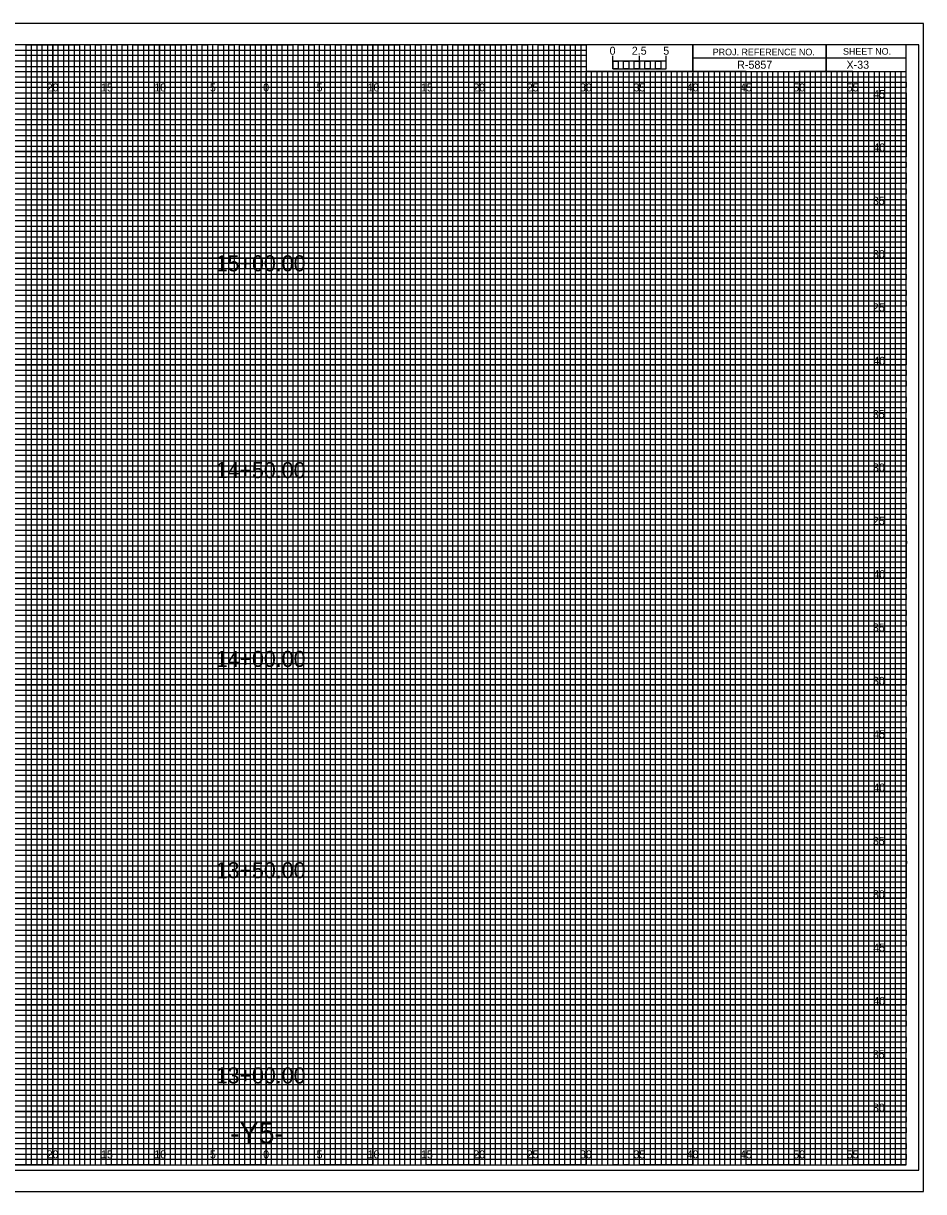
# Model space of a CAD drawing. Extents: x -7 to 162, y 107 to 217.
# Drawn here: x 77.2 to 161.7, y 107.5 to 217 of the extents above; entities that cross this region are included whole.
import ezdxf

# ---------------------------------------------------------------- set-up
doc = ezdxf.new("R2010")
doc.units = 0
for name, color, linetype in [('Exist Cross Section Cell', 7, 'Continuous'), ('Exist XS Center Line Elevation Label', 7, 'Continuous'), ('Exist XS Ground Line', 7, 'Continuous'), ('Prop CMT Pvmt Course 1', 7, 'Continuous'), ('Prop CMT Pvmt Course 1 Wedge', 7, 'Continuous'), ('Prop CMT Pvmt Course 2', 7, 'Continuous'), ('Prop CMT Pvmt Course 2 Wedge', 7, 'Continuous'), ('Prop CMT Pvmt Course 3', 7, 'Continuous'), ('Prop CMT Pvmt Surface', 7, 'Continuous'), ('Prop CMT Pvmt Surface Shoulder', 7, 'Continuous'), ('Prop CMT Pvmt Wedge Surface 1', 7, 'Continuous'), ('Prop CMT Shld Paved Course 1', 7, 'Continuous'), ('Prop CMT Shld Paved Course 2', 7, 'Continuous'), ('Prop CMT Shld Paved Course 3', 7, 'Continuous'), ('Prop CMT Slope Grass', 7, 'Continuous'), ('Prop CMT Subgrade Earthwork', 7, 'Continuous'), ('Scratch_Level_0', 7, 'Continuous')]:
    doc.layers.add(name, color=color, linetype=linetype)

msp = doc.modelspace()

# ---------------------------------------------------------------- linework, layer by layer
at = {"layer": 'Exist XS Center Line Elevation Label'}
for points in [[(72.5, 110), (77.5, 110), (77.5, 215), (82.5, 215), (82.5, 110), (87.5, 110), (87.5, 215), (92.5, 215), (92.5, 110), (97.5, 110), (97.5, 215), (102.5, 215), (102.5, 110), (107.5, 110), (107.5, 215), (112.5, 215), (112.5, 110), (117.5, 110), (117.5, 215), (122.5, 215), (122.5, 110), (127.5, 110), (127.5, 215), (129.97, 215), (130, 215), (130, 212.5), (132.5, 212.5), (132.5, 110), (137.5, 110), (137.5, 212.5), (142.5, 212.5), (142.5, 110), (147.5, 110), (147.5, 212.5), (152.5, 212.5), (152.5, 110), (157.5, 110), (157.5, 212.5)], [(0, 212.5), (137.5, 212.5)], [(0, 202.5), (160, 202.5), (160, 207.5), (0, 207.5)], [(0, 192.5), (160, 192.5), (160, 197.5), (0, 197.5)], [(0, 182.5), (160, 182.5), (160, 187.5), (0, 187.5)], [(0, 172.5), (160, 172.5), (160, 177.5), (0, 177.5)], [(0, 162.5), (160, 162.5), (160, 167.5), (0, 167.5)], [(0, 152.5), (160, 152.5), (160, 157.5), (0, 157.5)], [(0, 142.5), (160, 142.5), (160, 147.5), (0, 147.5)], [(0, 132.5), (160, 132.5), (160, 137.5), (0, 137.5)], [(0, 122.5), (160, 122.5), (160, 127.5), (0, 127.5)], [(0, 112.5), (160, 112.5), (160, 117.5), (0, 117.5)]]:
    msp.add_lwpolyline(points, dxfattribs=at)
at = {"layer": 'Exist XS Ground Line'}
for p, q in [((85, 215), (80, 215)), ((80, 215), (80, 110)), ((85, 110), (85, 215)), ((95, 215), (90, 215)), ((90, 215), (90, 110)), ((95, 110), (95, 215)), ((105, 215), (100, 215)), ((100, 215), (100, 110)), ((105, 110), (105, 215)), ((115, 215), (110, 215)), ((110, 215), (110, 110)), ((115, 110), (115, 215)), ((125, 215), (120, 215)), ((120, 215), (120, 110)), ((125, 110), (125, 215)), ((130, 215), (130, 110)), ((135, 110), (135, 212.5)), ((145, 212.5), (140, 212.5)), ((140, 212.5), (140, 110)), ((145, 110), (145, 212.5)), ((155, 212.5), (150, 212.5)), ((150, 212.5), (150, 110)), ((155, 110), (155, 212.5)), ((80, 110), (75, 110)), ((90, 110), (85, 110)), ((100, 110), (95, 110)), ((110, 110), (105, 110)), ((120, 110), (115, 110)), ((130, 110), (125, 110)), ((140, 110), (135, 110)), ((150, 110), (145, 110)), ((160, 110), (155, 110)), ((160, 110), (160, 110))]:
    msp.add_line(p, q, dxfattribs=at)
for points in [[(0, 210), (160, 210), (160, 205), (0, 205)], [(0, 200), (160, 200), (160, 195), (0, 195)], [(0, 190), (160, 190), (160, 185), (0, 185)], [(0, 180), (160, 180), (160, 175), (0, 175)], [(0, 170), (160, 170), (160, 165), (0, 165)], [(0, 160), (160, 160), (160, 155), (0, 155)], [(0, 150), (160, 150), (160, 145), (0, 145)], [(0, 140), (160, 140), (160, 135), (0, 135)], [(0, 130), (160, 130), (160, 125), (0, 125)], [(0, 120), (160, 120), (160, 115), (0, 115)]]:
    msp.add_lwpolyline(points, dxfattribs=at)
at = {"layer": 'Prop CMT Pvmt Course 1'}
msp.add_lwpolyline([(-5.4, 109.5), (161.2, 109.5), (161.2, 215), (-5.4, 215)], close=True, dxfattribs=at)
at = {"layer": 'Prop CMT Pvmt Course 2'}
for p, q in [((80, 110), (80, 215)), ((85, 110), (85, 215)), ((90, 110), (90, 215)), ((95, 110), (95, 215)), ((100, 110), (100, 215)), ((105, 110), (105, 215)), ((110, 110), (110, 215)), ((115, 110), (115, 215)), ((120, 110), (120, 215)), ((125, 110), (125, 215)), ((130, 110), (130, 212.34)), ((135, 110), (135, 212.34)), ((140, 110), (140, 212.34)), ((145, 110), (145, 212.34)), ((150, 110), (150, 212.34)), ((155, 110), (155, 212.34)), ((0, 210), (160, 210)), ((0, 205), (160, 205)), ((0, 200), (160, 200)), ((0, 195), (160, 195)), ((0, 190), (160, 190)), ((0, 185), (160, 185)), ((0, 180), (160, 180)), ((0, 175), (160, 175)), ((0, 170), (160, 170)), ((0, 165), (160, 165)), ((0, 160), (160, 160)), ((0, 155), (160, 155)), ((0, 150), (160, 150)), ((0, 145), (160, 145)), ((0, 140), (160, 140)), ((0, 135), (160, 135)), ((0, 130), (160, 130)), ((0, 125), (160, 125)), ((0, 120), (160, 120)), ((0, 115), (160, 115))]:
    msp.add_line(p, q, dxfattribs=at)
at = {"layer": 'Prop CMT Pvmt Course 3'}
for p, q in [((161.65, 217), (-6.7, 217)), ((-6.7, 107.5), (161.65, 107.5))]:
    msp.add_line(p, q, dxfattribs=at)
at = {"layer": 'Prop CMT Shld Paved Course 1'}
for p, q in [((133.5, 212.5), (133, 212.5)), ((133, 212.5), (133, 110)), ((133.5, 110), (133.5, 212.5)), ((134.5, 212.5), (134, 212.5)), ((134, 212.5), (134, 110)), ((134.5, 110), (134.5, 212.5)), ((133, 110), (132.5, 110)), ((134, 110), (133.5, 110))]:
    msp.add_line(p, q, dxfattribs=at)
for points in [[(77.5, 110), (78, 110), (78, 215), (78.5, 215), (78.5, 110)], [(78.5, 110), (79, 110), (79, 215), (79.5, 215), (79.5, 110)], [(80, 110), (80.5, 110), (80.5, 215), (81, 215), (81, 110)], [(81, 110), (81.5, 110), (81.5, 215), (82, 215), (82, 110)], [(82.5, 110), (83, 110), (83, 215), (83.5, 215), (83.5, 110)], [(83.5, 110), (84, 110), (84, 215), (84.5, 215), (84.5, 110)], [(85, 110), (85.5, 110), (85.5, 215), (86, 215), (86, 110)], [(86, 110), (86.5, 110), (86.5, 215), (87, 215), (87, 110)], [(87.5, 110), (88, 110), (88, 215), (88.5, 215), (88.5, 110)], [(88.5, 110), (89, 110), (89, 215), (89.5, 215), (89.5, 110)], [(90, 110), (90.5, 110), (90.5, 215), (91, 215), (91, 110)], [(91, 110), (91.5, 110), (91.5, 215), (92, 215), (92, 110)], [(92.5, 110), (93, 110), (93, 215), (93.5, 215), (93.5, 110)], [(93.5, 110), (94, 110), (94, 215), (94.5, 215), (94.5, 110)], [(95, 110), (95.5, 110), (95.5, 215), (96, 215), (96, 110)], [(96, 110), (96.5, 110), (96.5, 215), (97, 215), (97, 110)], [(97.5, 110), (98, 110), (98, 215), (98.5, 215), (98.5, 110)], [(98.5, 110), (99, 110), (99, 215), (99.5, 215), (99.5, 110)], [(100, 110), (100.5, 110), (100.5, 215), (101, 215), (101, 110)], [(101, 110), (101.5, 110), (101.5, 215), (102, 215), (102, 110)], [(102.5, 110), (103, 110), (103, 215), (103.5, 215), (103.5, 110)], [(103.5, 110), (104, 110), (104, 215), (104.5, 215), (104.5, 110)], [(105, 110), (105.5, 110), (105.5, 215), (106, 215), (106, 110)], [(106, 110), (106.5, 110), (106.5, 215), (107, 215), (107, 110)], [(107.5, 110), (108, 110), (108, 215), (108.5, 215), (108.5, 110)], [(108.5, 110), (109, 110), (109, 215), (109.5, 215), (109.5, 110)], [(110, 110), (110.5, 110), (110.5, 215), (111, 215), (111, 110)], [(111, 110), (111.5, 110), (111.5, 215), (112, 215), (112, 110)], [(112.5, 110), (113, 110), (113, 215), (113.5, 215), (113.5, 110)], [(113.5, 110), (114, 110), (114, 215), (114.5, 215), (114.5, 110)], [(115, 110), (115.5, 110), (115.5, 215), (116, 215), (116, 110)], [(116, 110), (116.5, 110), (116.5, 215), (117, 215), (117, 110)], [(117.5, 110), (118, 110), (118, 215), (118.5, 215), (118.5, 110)], [(118.5, 110), (119, 110), (119, 215), (119.5, 215), (119.5, 110)], [(120, 110), (120.5, 110), (120.5, 215), (121, 215), (121, 110)], [(121, 110), (121.5, 110), (121.5, 215), (122, 215), (122, 110)], [(122.5, 110), (123, 110), (123, 215), (123.5, 215), (123.5, 110)], [(123.5, 110), (124, 110), (124, 215), (124.5, 215), (124.5, 110)], [(125, 110), (125.5, 110), (125.5, 215), (126, 215), (126, 110)], [(126, 110), (126.5, 110), (126.5, 215), (127, 215), (127, 110)], [(127.5, 110), (128, 110), (128, 215), (128.5, 215), (128.5, 110)], [(128.5, 110), (129, 110), (129, 215), (129.5, 215), (129.5, 110)], [(130, 110), (130.5, 110), (130.5, 212.5), (131.01, 212.5), (131.01, 110)], [(131, 110), (131.5, 110), (131.5, 212.5), (132, 212.5), (132, 110)], [(135, 110), (135.49, 110), (135.49, 212.5), (136, 212.5), (136, 110)], [(136, 110), (136.5, 110), (136.5, 212.5), (137.03, 212.5), (137.03, 110)], [(137.5, 110), (138, 110), (138, 212.5), (138.5, 212.5), (138.5, 110)], [(138.5, 110), (139, 110), (139, 212.5), (139.5, 212.5), (139.5, 110)], [(140, 110), (140.5, 110), (140.5, 212.5), (141, 212.5), (141, 110)], [(141, 110), (141.5, 110), (141.5, 212.5), (142, 212.5), (142, 110)], [(142.5, 110), (143, 110), (143, 212.5), (143.5, 212.5), (143.5, 110)], [(143.5, 110), (144, 110), (144, 212.5), (144.5, 212.5), (144.5, 110)], [(145, 110), (145.5, 110), (145.5, 212.5), (146, 212.5), (146, 110)], [(146, 110), (146.5, 110), (146.5, 212.5), (147, 212.5), (147, 110)], [(147.5, 110), (148, 110), (148, 212.5), (148.5, 212.5), (148.5, 110)], [(148.5, 110), (149, 110), (149, 212.5), (149.5, 212.5), (149.5, 110)], [(150, 110), (150.5, 110), (150.5, 212.5), (151, 212.5), (151, 110)], [(151, 110), (151.5, 110), (151.5, 212.5), (152, 212.5), (152, 110)], [(152.5, 110), (153, 110), (153, 212.5), (153.5, 212.5), (153.5, 110)], [(153.5, 110), (154, 110), (154, 212.5), (154.5, 212.5), (154.5, 110)], [(155, 110), (155.5, 110), (155.5, 212.5), (156, 212.5), (156, 110)], [(156, 110), (156.5, 110), (156.5, 212.5), (157, 212.5), (157, 110)], [(157.5, 110), (158, 110), (158, 212.5), (158.5, 212.5), (158.5, 110)], [(158.5, 110), (159, 110), (159, 212.5), (159.5, 212.5), (159.5, 110)]]:
    msp.add_lwpolyline(points, dxfattribs=at)
at = {"layer": 'Prop CMT Shld Paved Course 2'}
for p, q in [((132.5, 212.75), (132.5, 213.95)), ((132.5, 213.45), (132.5, 213.95)), ((135, 212.75), (135, 213.95)), ((137.5, 212.75), (137.5, 213.95)), ((137.5, 213.45), (137.5, 213.95))]:
    msp.add_line(p, q, dxfattribs=at)
for points in [[(137.5, 213.45), (132.5, 213.45), (132.5, 212.75), (137.5, 212.75)], [(132.5, 213.45), (133, 213.45), (133, 212.75), (132.5, 212.75)], [(133.5, 213.45), (134, 213.45), (134, 212.75), (133.5, 212.75)], [(134.5, 213.45), (135, 213.45), (135, 212.75), (134.5, 212.75)], [(135.5, 213.45), (136, 213.45), (136, 212.75), (135.5, 212.75)], [(136.5, 213.45), (137, 213.45), (137, 212.75), (136.5, 212.75)]]:
    msp.add_lwpolyline(points, close=True, dxfattribs=at)
at = {"layer": 'Prop CMT Shld Paved Course 3'}
msp.add_lwpolyline([(-6.7, 107.5), (161.65, 107.5), (161.65, 217), (-6.7, 217)], close=True, dxfattribs=at)
at = {"layer": 'Prop CMT Slope Grass'}
for p, q in [((152.5, 215), (152.5, 212.5)), ((152.5, 212.5), (152.5, 215)), ((160, 213.75), (140, 213.75)), ((140, 213.75), (140, 212.5)), ((140, 212.5), (160, 212.5))]:
    msp.add_line(p, q, dxfattribs=at)
for points in [[(160, 215), (0, 215), (0, 110), (160, 110)], [(140, 215), (130, 215), (130, 212.52), (140, 212.52)], [(160, 215), (140, 215), (140, 212.5), (160, 212.5)]]:
    msp.add_lwpolyline(points, close=True, dxfattribs=at)
at = {"layer": 'Scratch_Level_0'}
for p, q in [((0, 214.5), (130, 214.5)), ((130, 213.99), (0, 213.99)), ((130, 214.5), (130, 213.99)), ((0, 213.5), (130, 213.5)), ((130, 212.94), (0, 212.94)), ((130, 213.5), (130, 212.94)), ((0, 212), (160, 212))]:
    msp.add_line(p, q, dxfattribs=at)
for points in [[(0, 211.5), (135, 211.5), (160, 211.5), (160, 211), (0, 211)], [(0, 210.5), (160, 210.5), (160, 209.5), (0, 209.5)], [(0, 209), (160, 209), (160, 208.5), (0, 208.49)], [(0, 208), (160, 208), (160, 207), (0, 207)], [(0, 206.5), (160, 206.5), (160, 206), (0, 206)], [(0, 205.5), (160, 205.5), (160, 204.5), (0, 204.5)], [(0, 204), (160, 204), (160, 203.5), (0, 203.5)], [(0, 203), (160, 203), (160, 202), (0, 202)], [(0, 201.5), (160, 201.5), (160, 201), (0, 201)], [(0, 200.5), (160, 200.5), (160, 199.5), (0, 199.5)], [(0, 199), (160, 199), (160, 198.5), (0, 198.5)], [(0, 198), (160, 198), (160, 196.97), (160, 196.5), (160, 196), (0, 196)], [(0, 197), (160, 197), (160, 196.5), (0, 196.5)], [(0, 195.5), (160, 195.5), (160, 194.5), (0, 194.52)], [(0, 194.52), (160, 194.5), (160, 194), (0, 194)], [(0, 193.5), (160, 193.5), (160, 193), (0, 193)], [(0, 192), (160, 192), (160, 191.5), (0, 191.5)], [(0, 191), (160, 191), (160, 190.5), (0, 190.5)], [(-0.04, 189.44), (160, 189.44), (160, 188.94), (-0.04, 188.94)], [(0, 188.5), (160, 188.5), (160, 188), (0, 188)], [(0, 187), (160, 187), (160, 186.5), (0, 186.5)], [(0, 186), (160, 186), (160, 185.5), (0, 185.5)], [(0, 184.5), (160, 184.5), (160, 184), (0, 184)], [(0, 183.5), (160, 183.5), (160, 183), (0, 183)], [(0, 182), (160, 182), (160, 181.5), (0, 181.5)], [(0, 181), (160, 181), (160, 180.5), (0, 180.5)], [(0, 179.5), (160, 179.5), (160, 178.99), (0, 179)], [(0, 178.5), (160, 178.5), (160, 178), (0, 178)], [(0, 177), (160, 177), (160, 176.5), (0, 176.5)], [(0, 176), (160, 176), (160, 175.5), (0, 175.5)], [(0, 174.5), (160, 174.5), (160, 174), (0, 174)], [(0, 173.5), (160, 173.5), (160, 173), (0, 173)], [(0, 172), (160, 172), (160, 171.5), (0, 171.5)], [(0, 171), (160, 171), (160, 170.5), (0, 170.5)], [(0, 169.5), (160, 169.5), (160, 169), (0, 169)], [(0, 168.5), (160.03, 168.46), (160, 168), (0, 168)], [(0, 167), (160, 167), (160, 166.5), (0, 166.5)], [(0, 166), (160, 166), (160, 165.5), (0, 165.5)], [(0, 164.5), (160, 164.5), (160, 164), (0, 164)], [(0, 163.5), (160, 163.5), (160, 163), (0, 163)], [(0, 162), (160, 162), (160, 161.5), (0, 161.5)], [(0, 161), (160, 161), (160, 160.5), (0, 160.5)], [(0, 159.5), (160, 159.5), (160, 159), (0, 159)], [(0, 158.5), (160, 158.5), (160, 158), (0, 158)], [(0, 157), (160, 157), (160, 156.5), (0, 156.5)], [(0, 156), (160, 156), (160, 155.5), (0, 155.5)], [(0, 154.5), (160, 154.5), (160, 154), (0, 154)], [(0, 153.5), (160, 153.5), (160, 153), (0, 153)], [(0, 152), (160, 152), (160, 151.5), (0, 151.5)], [(0, 151), (160, 151), (160, 150.5), (0, 150.5)], [(0, 149.5), (160, 149.5), (160, 148.99), (0, 149)], [(0, 148.5), (160, 148.5), (160, 148), (0, 148)], [(0, 147), (160, 147), (160, 146.5), (0, 146.5)], [(0, 146), (160, 146), (160, 145.5), (0, 145.5)], [(0, 144.5), (160, 144.5), (160, 144), (0, 144)], [(0, 143.5), (160, 143.5), (160, 143), (0, 143)], [(0, 142), (160, 142), (160, 141.5), (0, 141.5)], [(0, 141), (160, 141), (160, 140.5), (0, 140.5)], [(0, 139.5), (160, 139.5), (160, 139), (0, 139)], [(0, 138.5), (160.03, 138.46), (160, 138), (0, 138)], [(0, 137), (160, 137), (160, 136.5), (0, 136.5)], [(0, 136), (160, 136), (160, 135.5), (0, 135.5)], [(0, 134.5), (160, 134.5), (160, 134), (0, 134)], [(0, 133.5), (160, 133.5), (160, 133), (0, 133)], [(0, 132), (160, 132), (160, 131.5), (0, 131.5)], [(0, 131), (160, 131), (160, 130.5), (0, 130.5)], [(0, 129.5), (160, 129.5), (160, 129), (0, 129)], [(0, 128.5), (160, 128.5), (160, 128), (0, 128)], [(0, 127), (160, 127), (160, 126.5), (0, 126.5)], [(0, 126), (160, 126), (160, 125.5), (0, 125.5)], [(0, 124.5), (160, 124.5), (160, 124), (0, 124)], [(0, 123.5), (160, 123.5), (160, 123), (0, 123)], [(0, 122), (160, 122), (160, 121.5), (0, 121.5)], [(0, 121), (160, 121), (160, 120.5), (0, 120.5)], [(0, 119.5), (160, 119.5), (160, 119), (0, 119)], [(0, 118.5), (160, 118.5), (160, 118), (0, 118)], [(0, 117), (160, 117), (160, 116.5), (0, 116.5)], [(0, 116), (160, 116), (160, 115.5), (0, 115.5)], [(0, 114.5), (160, 114.5), (160, 114), (0, 114)], [(0, 113.5), (160, 113.5), (160, 113), (0, 113)], [(0, 112), (160, 112), (160, 111.5), (0, 111.5)], [(0, 111), (160, 111), (160, 110.5), (0, 110.5)]]:
    msp.add_lwpolyline(points, dxfattribs=at)

# ---------------------------------------------------------------- texts
at = {"layer": 'Exist Cross Section Cell'}
for s, p in [('20', (79.43, 210.62)), ('15', (84.53, 210.62)), ('10', (89.52, 210.62)), ('5', (94.74, 210.62)), ('0', (99.73, 210.62)), ('0', (99.73, 210.62)), ('5', (104.74, 210.62)), ('10', (109.52, 210.62)), ('15', (114.53, 210.62)), ('20', (119.43, 210.62)), ('25', (124.44, 210.62)), ('30', (129.43, 210.62)), ('35', (134.44, 210.62)), ('40', (139.43, 210.62)), ('45', (144.44, 210.62)), ('50', (149.43, 210.62)), ('55', (154.44, 210.62)), ('20', (79.43, 110.62)), ('15', (84.53, 110.62)), ('10', (89.52, 110.62)), ('5', (94.74, 110.62)), ('0', (99.73, 110.62)), ('0', (99.73, 110.62)), ('5', (104.74, 110.62)), ('10', (109.52, 110.62)), ('15', (114.53, 110.62)), ('20', (119.43, 110.62)), ('25', (124.44, 110.62)), ('30', (129.43, 110.62)), ('35', (134.44, 110.62)), ('40', (139.43, 110.62)), ('45', (144.44, 110.62)), ('50', (149.43, 110.62)), ('55', (154.44, 110.62))]:
    msp.add_text(s, height=0.75, dxfattribs=at).set_placement(p)
at = {"layer": 'Prop CMT Pvmt Course 1 Wedge'}
msp.add_text('R-5857', height=0.75, dxfattribs=at).set_placement((144.17, 212.75))
at = {"layer": 'Prop CMT Pvmt Course 2 Wedge'}
msp.add_text('-Y5-', height=2, dxfattribs=at).set_placement((96.63, 112))
at = {"layer": 'Prop CMT Pvmt Surface'}
msp.add_text('X-33', height=0.75, dxfattribs=at).set_placement((154.42, 212.75))
at = {"layer": 'Prop CMT Pvmt Surface Shoulder'}
for s, p in [('15+00.00', (95.28, 193.76)), ('14+50.00', (95.28, 174.38)), ('14+00.00', (95.28, 156.68)), ('13+50.00', (95.28, 136.88)), ('13+00.00', (95.28, 117.64))]:
    msp.add_text(s, height=1.5, dxfattribs=at).set_placement(p)
at = {"layer": 'Prop CMT Pvmt Wedge Surface 1'}
for s, p in [('2.5', (134.29, 214.06)), ('5', (137.24, 214.06))]:
    msp.add_text(s, height=0.75, dxfattribs=at).set_placement(p)
at = {"layer": 'Prop CMT Shld Paved Course 2'}
msp.add_text('0', height=0.75, dxfattribs=at).set_placement((132.21, 214.06))
at = {"layer": 'Prop CMT Slope Grass'}
for s, p in [('PROJ. REFERENCE NO.', (141.88, 214)), ('SHEET NO.', (154.09, 214.06))]:
    msp.add_text(s, height=0.625, dxfattribs=at).set_placement(p)
at = {"layer": 'Prop CMT Subgrade Earthwork'}
for s, p in [('45', (156.92, 210)), ('40', (156.93, 205)), ('35', (156.88, 200)), ('30', (156.89, 195)), ('25', (156.89, 190)), ('40', (156.93, 185)), ('35', (156.88, 180)), ('30', (156.89, 175)), ('25', (156.89, 170)), ('40', (156.93, 165)), ('35', (156.88, 160)), ('30', (156.89, 155)), ('45', (156.92, 150)), ('40', (156.93, 145)), ('35', (156.88, 140)), ('30', (156.89, 135)), ('45', (156.92, 130)), ('40', (156.93, 125)), ('35', (156.88, 120)), ('30', (156.89, 115))]:
    msp.add_text(s, height=0.75, dxfattribs=at).set_placement(p)

doc.saveas('drawing.dxf')
